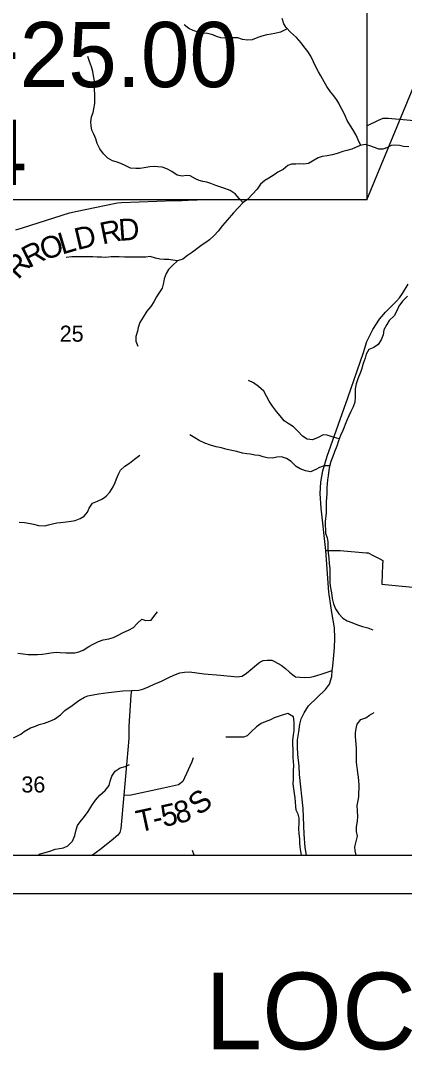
# Model space of a CAD drawing. Extents: x 0 to 34, y 0 to 22.
# Drawn here: x 3.888 to 4.889, y 13.591 to 16.276 of the extents above; entities that cross this region are included whole.
import ezdxf

# ---------------------------------------------------------------- set-up
doc = ezdxf.new("R2010")
doc.units = 0
for name, color, linetype in [('GM_X_County_Road', 7, 'Continuous'), ('GM_X_Minor_River', 7, 'Continuous'), ('GM_X_Section_Text', 7, 'Continuous'), ('GM_X_State_Route', 7, 'Continuous'), ('GM_X_Township_Road', 7, 'Continuous'), ('GM_X_Township_Road_Text', 7, 'Continuous'), ('SH_Data', 7, 'Continuous'), ('SH_Text', 7, 'Continuous')]:
    doc.layers.add(name, color=color, linetype=linetype)

msp = doc.modelspace()

# ---------------------------------------------------------------- linework, layer by layer
at = {"layer": 'GM_X_County_Road'}
for points in [[(4.4587, 14.5656), (4.466, 14.5663), (4.4773, 14.5745), (4.4914, 14.5865), (4.5038, 14.5973), (4.5115, 14.6033), (4.5206, 14.6075), (4.5304, 14.6087), (4.5428, 14.6081), (4.5498, 14.6046), (4.5676, 14.5951), (4.5786, 14.5868), (4.5894, 14.5769), (4.5977, 14.5704), (4.6051, 14.5653), (4.6162, 14.5643), (4.6291, 14.5635), (4.6431, 14.5637), (4.652, 14.5657), (4.6718, 14.572), (4.7006, 14.5812)], [(3.8693, 14.4063), (3.8887, 14.4153), (3.8972, 14.422), (3.9132, 14.4322), (3.9264, 14.4366), (3.9364, 14.4403), (3.95, 14.4445), (3.964, 14.4496), (3.9762, 14.4543), (3.9917, 14.4661), (4.0034, 14.4769), (4.0227, 14.49), (4.0395, 14.5031), (4.0541, 14.512), (4.0635, 14.5158), (4.0911, 14.5205), (4.1174, 14.5242), (4.1544, 14.5285), (4.1768, 14.5291), (4.1962, 14.5298), (4.2064, 14.5324), (4.2211, 14.5391), (4.2379, 14.5464), (4.2532, 14.553), (4.2693, 14.5603), (4.278, 14.5646), (4.2919, 14.5713), (4.3033, 14.5753), (4.3156, 14.5772), (4.3282, 14.5776), (4.3669, 14.5729), (4.4089, 14.5691), (4.4536, 14.5652), (4.4587, 14.5656)]]:
    msp.add_lwpolyline(points, dxfattribs=at)
at = {"layer": 'GM_X_Minor_River'}
msp.add_line((4.3406, 14.1), (4.3363, 14.1118), dxfattribs=at)
for points in [[(4.7754, 15.9506), (4.7684, 15.9651), (4.7632, 15.9776), (4.7545, 15.9917), (4.7485, 16.0016), (4.7398, 16.0156), (4.735, 16.0259), (4.729, 16.0388), (4.7218, 16.051), (4.7181, 16.0608), (4.712, 16.0703), (4.7049, 16.0798), (4.6962, 16.0905), (4.6864, 16.1045), (4.6797, 16.1163), (4.671, 16.1315), (4.665, 16.1425), (4.6594, 16.152), (4.6519, 16.1687), (4.6444, 16.1832), (4.6368, 16.1957), (4.6263, 16.2086), (4.6199, 16.2181), (4.6071, 16.2318), (4.592, 16.2455), (4.58, 16.2577), (4.5739, 16.2676), (4.5702, 16.2812)], [(4.583, 16.2546), (4.5655, 16.246), (4.5511, 16.2423), (4.5409, 16.2404), (4.53, 16.2389), (4.5167, 16.2352), (4.5068, 16.2318), (4.4921, 16.2262), (4.4796, 16.2251), (4.4667, 16.227), (4.4539, 16.2313), (4.444, 16.2313), (4.4308, 16.2306), (4.4206, 16.2299), (4.4096, 16.231), (4.399, 16.2345), (4.3888, 16.2391), (4.3756, 16.2425), (4.3628, 16.243), (4.3522, 16.2445), (4.3382, 16.2499), (4.3265, 16.2556), (4.314, 16.2648)], [(4.4678, 15.8009), (4.4576, 15.812), (4.4471, 15.8242), (4.4339, 15.8326), (4.4207, 15.8379), (4.3969, 15.846), (4.384, 15.8509), (4.3734, 15.8544), (4.3632, 15.8563), (4.3534, 15.8594), (4.3436, 15.8632), (4.33, 15.8708), (4.3202, 15.872), (4.3088, 15.8705), (4.2963, 15.8725), (4.282, 15.8824), (4.2688, 15.8893), (4.2567, 15.8939), (4.2457, 15.895), (4.2359, 15.8951), (4.2245, 15.8947), (4.2098, 15.8918), (4.1992, 15.8907), (4.1882, 15.8899), (4.1746, 15.8915), (4.1621, 15.8969), (4.1489, 15.903), (4.1372, 15.9076), (4.1274, 15.9106), (4.1149, 15.9171), (4.1036, 15.9285), (4.0942, 15.9418), (4.0878, 15.9555), (4.0837, 15.9673), (4.0784, 15.9798), (4.0739, 15.9904), (4.0717, 16.0018), (4.0706, 16.0117), (4.0729, 16.0249), (4.0771, 16.0359), (4.0791, 16.0458), (4.0814, 16.0594), (4.081, 16.0704), (4.0811, 16.0844), (4.0808, 16.095), (4.0808, 16.1056), (4.0801, 16.1185), (4.0779, 16.1318), (4.0764, 16.1436), (4.073, 16.155), (4.0678, 16.1694), (4.0629, 16.1827)], [(4.9004, 15.9468), (4.886, 15.948), (4.8762, 15.9507), (4.8641, 15.9515), (4.8542, 15.9504), (4.8447, 15.9451), (4.8326, 15.9406), (4.822, 15.9406), (4.8111, 15.9452), (4.7982, 15.9498), (4.7861, 15.9525), (4.7736, 15.9503), (4.7611, 15.9447), (4.7513, 15.9409), (4.7384, 15.9375), (4.7278, 15.9342), (4.713, 15.9297), (4.7005, 15.9259), (4.6869, 15.9237), (4.674, 15.9215), (4.6642, 15.9177), (4.6384, 15.9034), (4.6267, 15.902), (4.6157, 15.9028), (4.6055, 15.902), (4.5945, 15.9013), (4.5843, 15.8979), (4.5722, 15.8881), (4.5585, 15.8806), (4.549, 15.8734), (4.5354, 15.8655), (4.5248, 15.8591), (4.5138, 15.8493), (4.5046, 15.8361), (4.4929, 15.8236), (4.4799, 15.8096), (4.4686, 15.8017), (4.4553, 15.7874), (4.4431, 15.7749), (4.4264, 15.7553), (4.4142, 15.742), (4.4028, 15.7273), (4.393, 15.716), (4.3801, 15.7039), (4.3706, 15.6971), (4.3611, 15.6911), (4.3505, 15.6835), (4.3364, 15.6718), (4.3232, 15.6639), (4.3106, 15.6541), (4.2974, 15.65), (4.2845, 15.6515), (4.2743, 15.6527), (4.2626, 15.6531), (4.2509, 15.6543), (4.2399, 15.6566), (4.2259, 15.6605), (4.2142, 15.6594), (4.2025, 15.659), (4.1862, 15.6595), (4.1688, 15.6592), (4.1586, 15.6592), (4.1446, 15.6604), (4.1344, 15.6604), (4.1242, 15.6597), (4.1094, 15.6586), (4.0984, 15.659), (4.0875, 15.6591), (4.0765, 15.6599), (4.0621, 15.6603), (4.0459, 15.66), (4.0356, 15.66), (4.0213, 15.6601), (4.0065, 15.6579)], [(4.2974, 15.65), (4.2837, 15.6375), (4.2735, 15.6266), (4.267, 15.6164), (4.262, 15.6023), (4.2605, 15.5921), (4.257, 15.5781), (4.2483, 15.5656), (4.2418, 15.5554), (4.2353, 15.5429), (4.227, 15.5305), (4.2171, 15.518), (4.2072, 15.5029), (4.1988, 15.4889), (4.1946, 15.4756), (4.1923, 15.4658), (4.1885, 15.4525), (4.1884, 15.4404), (4.1933, 15.4267)], [(4.897, 15.5575), (4.8837, 15.5447)], [(4.8837, 15.5447), (4.8742, 15.5314), (4.8697, 15.5208), (4.862, 15.5065), (4.8487, 15.4936), (4.8427, 15.4838), (4.8354, 15.4698), (4.8331, 15.4569), (4.8281, 15.4437), (4.8205, 15.4312), (4.8088, 15.4237), (4.7959, 15.418), (4.789, 15.4059), (4.786, 15.3957), (4.7814, 15.3817), (4.7764, 15.3665), (4.773, 15.3563), (4.7669, 15.3416), (4.7626, 15.3291), (4.7599, 15.3154), (4.7607, 15.3056), (4.7606, 15.2946), (4.7591, 15.2809), (4.7552, 15.2688), (4.7491, 15.2563), (4.7442, 15.2457), (4.7381, 15.2317), (4.7281, 15.2071), (4.7224, 15.1943), (4.7167, 15.1799), (4.7125, 15.1663), (4.7068, 15.1515), (4.7018, 15.1398), (4.6968, 15.1265), (4.693, 15.1137), (4.6914, 15.1034), (4.6895, 15.0894), (4.6883, 15.0784), (4.6867, 15.058), (4.6863, 15.0432), (4.6855, 15.0314), (4.6851, 15.022), (4.685, 15.0072), (4.6846, 14.9924), (4.6823, 14.9697), (4.6822, 14.9594), (4.6826, 14.9492), (4.6833, 14.9397), (4.687, 14.9272), (4.6889, 14.9166), (4.6892, 14.9022), (4.6903, 14.8893), (4.6917, 14.8741), (4.6928, 14.8605), (4.6939, 14.8472), (4.6942, 14.8324), (4.6946, 14.8184), (4.6945, 14.8089), (4.696, 14.7968), (4.6982, 14.7839), (4.7004, 14.7691), (4.7042, 14.755), (4.7086, 14.7421), (4.7173, 14.7292), (4.7279, 14.7178), (4.7396, 14.7106), (4.752, 14.7067), (4.7664, 14.7006), (4.7792, 14.696), (4.7936, 14.6929), (4.8068, 14.6872)], [(4.719, 15.1856), (4.7005, 15.1909), (4.6869, 15.1952), (4.6767, 15.1956), (4.6638, 15.1892), (4.6486, 15.1828), (4.635, 15.1848), (4.6233, 15.1928), (4.6112, 15.2057), (4.5999, 15.2167), (4.5852, 15.2251), (4.575, 15.2327), (4.5645, 15.2453), (4.5555, 15.2571), (4.5449, 15.2708), (4.5359, 15.2837), (4.5291, 15.297), (4.522, 15.3095), (4.5084, 15.3221), (4.4948, 15.3312), (4.4824, 15.3373)], [(4.6933, 15.1148), (4.6794, 15.1148), (4.6673, 15.1103), (4.6578, 15.1054), (4.6438, 15.0994), (4.6305, 15.1021), (4.6173, 15.1075), (4.6067, 15.1132), (4.5932, 15.1262), (4.5811, 15.1342), (4.5686, 15.1388), (4.5558, 15.1373), (4.5444, 15.1351), (4.5304, 15.1359), (4.5202, 15.1386), (4.5096, 15.1416), (4.4987, 15.1432), (4.4873, 15.1459), (4.4775, 15.1467), (4.4665, 15.1479), (4.4518, 15.1521), (4.4344, 15.1563), (4.4234, 15.1586), (4.4113, 15.1617), (4.3977, 15.1644), (4.3826, 15.1686), (4.3683, 15.174), (4.3535, 15.1813), (4.3418, 15.1881), (4.3294, 15.1961)], [(3.884, 14.9685), (3.898, 14.9669), (3.9086, 14.9657), (3.9215, 14.9634), (3.9347, 14.9596), (3.9506, 14.9588), (3.9604, 14.961), (3.971, 14.964), (3.982, 14.9662), (3.9919, 14.9673), (4.0066, 14.9692), (4.0195, 14.9706), (4.0301, 14.9729), (4.0433, 14.9777), (4.0532, 14.9838), (4.0619, 14.9943), (4.0665, 15.0046), (4.0756, 15.0174), (4.0885, 15.0231), (4.1018, 15.0291), (4.1113, 15.0359), (4.1208, 15.0464), (4.1288, 15.0601), (4.1345, 15.0718), (4.1375, 15.0816), (4.1429, 15.0937), (4.1486, 15.1039), (4.1596, 15.1141), (4.1717, 15.1221), (4.1846, 15.1322), (4.199, 15.1428)], [(3.8809, 14.627), (3.8945, 14.6247), (3.9074, 14.6235), (3.9316, 14.6234), (3.9452, 14.6241), (3.9558, 14.6256), (3.9664, 14.6278), (3.9804, 14.6289), (3.991, 14.6285), (4.0065, 14.6273), (4.0292, 14.6272), (4.0398, 14.6302), (4.0511, 14.6343), (4.0656, 14.6441), (4.0773, 14.6505), (4.091, 14.6573), (4.1031, 14.661), (4.1175, 14.6636), (4.1303, 14.6674), (4.1409, 14.6723), (4.155, 14.6806), (4.169, 14.6866), (4.1823, 14.6937), (4.1921, 14.7039), (4.2039, 14.7152), (4.2141, 14.7122), (4.2281, 14.7125), (4.2353, 14.7223), (4.2444, 14.7344)], [(4.6204, 14.1), (4.6189, 14.1107), (4.6171, 14.1209), (4.616, 14.1323), (4.6156, 14.1425), (4.6145, 14.1558), (4.6135, 14.1695), (4.6143, 14.1835), (4.6143, 14.1967), (4.6117, 14.207), (4.6068, 14.2169), (4.6054, 14.2271), (4.6046, 14.2388), (4.6035, 14.2491), (4.6025, 14.2605), (4.6002, 14.2733), (4.5984, 14.2862), (4.5992, 14.2972), (4.5996, 14.3097), (4.5993, 14.3192), (4.6001, 14.3336), (4.5997, 14.3442), (4.599, 14.3548), (4.5987, 14.3677), (4.5983, 14.3776), (4.598, 14.3871), (4.5977, 14.3992), (4.5996, 14.4136), (4.6012, 14.4242), (4.6016, 14.4378), (4.6016, 14.4477), (4.5994, 14.4602), (4.5851, 14.469), (4.5726, 14.466), (4.5597, 14.4619), (4.5495, 14.4577), (4.5392, 14.4528), (4.5252, 14.4472), (4.5154, 14.4431), (4.5032, 14.4344), (4.4903, 14.4223), (4.4789, 14.411), (4.4695, 14.4072), (4.4577, 14.408), (4.4456, 14.4077), (4.4233, 14.4078)], [(4.7633, 14.1), (4.7604, 14.1109), (4.7593, 14.1215), (4.7631, 14.1352), (4.7662, 14.1492), (4.7636, 14.1617), (4.7637, 14.1734), (4.7664, 14.1886), (4.7672, 14.2011), (4.7661, 14.2159), (4.7658, 14.2295), (4.7681, 14.2428), (4.7696, 14.2522), (4.77, 14.2636), (4.7705, 14.2731), (4.7705, 14.2833), (4.7702, 14.2932), (4.7687, 14.3038), (4.7672, 14.3136), (4.7665, 14.3235), (4.7646, 14.3341), (4.7635, 14.344), (4.7636, 14.3641), (4.764, 14.3785), (4.7633, 14.3891), (4.7622, 14.3993), (4.7615, 14.4092), (4.7608, 14.4186), (4.7627, 14.43), (4.7658, 14.4418), (4.7753, 14.4538), (4.7882, 14.458), (4.7977, 14.4648), (4.8098, 14.4719)], [(4.0366, 14.1769), (4.0434, 14.1868), (4.0548, 14.2004), (4.064, 14.2136), (4.0739, 14.2291), (4.083, 14.2435), (4.0948, 14.2563), (4.1084, 14.2684), (4.1191, 14.282), (4.1218, 14.293), (4.1256, 14.3062), (4.1343, 14.3194), (4.1472, 14.3274), (4.1605, 14.3311), (4.1722, 14.3364)], [(3.9328, 14.1), (3.9391, 14.103), (3.952, 14.1071), (3.9664, 14.1116), (3.9781, 14.1158), (3.9895, 14.1176), (4.0001, 14.1187), (4.0107, 14.124), (4.0228, 14.1368), (4.0289, 14.1512), (4.0331, 14.1663), (4.0366, 14.1769)]]:
    msp.add_lwpolyline(points, dxfattribs=at)
at = {"layer": 'GM_X_State_Route'}
msp.add_lwpolyline([(4.6332, 14.1), (4.6301, 14.1198), (4.6269, 14.1548), (4.6248, 14.2213), (4.6154, 14.3101), (4.6142, 14.3324), (4.6107, 14.3623), (4.6097, 14.3821), (4.6101, 14.4007), (4.6134, 14.4217), (4.6162, 14.4419), (4.6191, 14.4557), (4.6269, 14.4712), (4.6384, 14.4893), (4.6832, 14.5317), (4.6934, 14.546), (4.6992, 14.5654), (4.7006, 14.5812), (4.7022, 14.593), (4.7061, 14.6407), (4.7072, 14.6655), (4.7061, 14.6925), (4.6998, 14.7324), (4.6913, 14.7854), (4.6838, 14.8946), (4.6712, 15.0047), (4.6694, 15.0426), (4.6708, 15.0721), (4.6758, 15.1017), (4.6873, 15.14), (4.7415, 15.2924), (4.7818, 15.4108), (4.7909, 15.4392), (4.8065, 15.4704), (4.8241, 15.4979), (4.8391, 15.5158), (4.8679, 15.5448), (4.8762, 15.5535), (4.8838, 15.5646), (4.8989, 15.5885)], dxfattribs=at)
at = {"layer": 'GM_X_Township_Road'}
msp.add_line((4.2894, 15.8068), (4.2896, 15.8085), dxfattribs=at)
for points in [[(4.7911, 16.0016), (4.8212, 16.0162), (4.8333, 16.0212), (4.8461, 16.0212), (5.0986, 15.999), (5.1312, 15.998), (5.1718, 15.9947)], [(3.8754, 15.7301), (3.8931, 15.7358), (4.0155, 15.7749), (4.0349, 15.779), (4.1316, 15.7994), (4.1402, 15.8012), (4.1511, 15.8016), (4.2894, 15.8068), (4.3086, 15.8069), (4.3246, 15.808), (4.3388, 15.8083), (4.3483, 15.8085)], [(4.6838, 14.8946), (4.7216, 14.8947), (4.7892, 14.8879), (4.7938, 14.8878), (4.8071, 14.8811), (4.8246, 14.8722), (4.8322, 14.8684), (4.8317, 14.8573), (4.83, 14.8083), (4.8299, 14.8065), (4.8475, 14.8048), (4.9548, 14.7948)], [(4.1768, 14.5291), (4.1751, 14.517), (4.1698, 14.4366), (4.1704, 14.4233), (4.1704, 14.4039), (4.1571, 14.2564), (4.1492, 14.1691), (4.1462, 14.1589), (4.1416, 14.1522), (4.1242, 14.1373), (4.0942, 14.1136), (4.0753, 14.1)], [(4.3375, 14.3534), (4.3345, 14.3434), (4.3108, 14.2921), (4.2995, 14.2837), (4.2604, 14.275), (4.1715, 14.2557), (4.1571, 14.2564)]]:
    msp.add_lwpolyline(points, dxfattribs=at)
at = {"layer": 'SH_Data'}
for p, q in [((2.1, 14.1), (8.9, 14.1)), ((2, 14), (9, 14))]:
    msp.add_line(p, q, dxfattribs=at)
at = {"layer": 'SH_Text'}
for points in [[(4.7911, 16.5585), (4.7911, 15.8085), (5.3209, 17.091)], [(2.7795, 16.5585), (4.7911, 16.5585), (4.7911, 15.8085), (2.7795, 15.8085)]]:
    msp.add_lwpolyline(points, close=True, dxfattribs=at)

# ---------------------------------------------------------------- texts
at = {"layer": 'GM_X_Section_Text'}
for s, p in [('25', (3.9899, 15.4387)), ('36', (3.8899, 14.2633))]:
    msp.add_text(s, height=0.04186, rotation=0, dxfattribs=at).set_placement(p)
at = {"layer": 'GM_X_Township_Road_Text'}
for s, rotation, p in [('D', 13.2049, (4.0357, 15.6774)), ('R', 11.6283, (4.1012, 15.6922)), ('D', 4.0833, (4.1449, 15.7014)), ('O', 18.0018, (3.9487, 15.6501)), ('L', 16.6254, (3.9959, 15.6654)), ('R', 26.9525, (3.9092, 15.6298)), ('R', 47.0565, (3.8816, 15.5988)), ('S', 38.5258, (4.3532, 14.2013)), ('5', 12.3856, (4.2603, 14.173)), ('8', 14.601, (4.2966, 14.181)), ('T', 12.2282, (4.1961, 14.1591)), ('-', 12.2624, (4.2376, 14.1681))]:
    msp.add_text(s, height=0.0568, rotation=rotation, dxfattribs=at).set_placement(p)
at = {"layer": 'SH_Text'}
for s, height, p in [('STA. 551+25.00', 0.17, (2.8051, 16.1024)), ('SLM 10.44', 0.17, (2.8051, 15.8474)), ('LOCATION MAP', 0.2, (4.3691, 13.5938))]:
    msp.add_text(s, height=height, dxfattribs=at).set_placement(p)

doc.saveas('drawing.dxf')
